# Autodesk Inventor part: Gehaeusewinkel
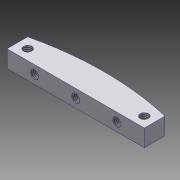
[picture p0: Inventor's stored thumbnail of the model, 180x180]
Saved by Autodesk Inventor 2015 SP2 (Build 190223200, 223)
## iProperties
Created: 2016-03
Part Number: Gehaeusewinkel
Material: Aluminum 6061
Document SubType Name: Modeling
Designer: rYan
Mass: 3.65288 g
Surface Area: 12.7601 cm^2
Volume: 1.35292 cm^3
Density: 2.7 g/cm^3
Appearance: Aluminum - Flat
Author: rYan
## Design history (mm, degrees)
sketch "Skizze5"
  geometry: L1 (-20, 0)-(20, 0); L2 (20, 0)-(20, 6); L3 (-20, 0)-(-20, 6); L4 (0, 25.73)-(0, -96.07) reference; L5 (-28, 0)-(28, 0) reference; A1 r 87 centre (0, -78.67) between (20, 6) and (-20, 6); 1 further point
  constraints: 6 end point, 2 point on circle, 1 centre point, 1 collinear, 1 horizontal, 1 perpendicular, 1 point on line, 1 vertical, 1 other
  dimensions: "d39" = 87 radius of A1; "d40" = 40 distance of L1.start L1.end; "d41" = 6 distance of L1.end L2.end
extrude "Extrusion2" new body sketch "Skizze5" distance "d42" = 5; taper "d43" = 0 deg
sketch "Skizze6"
  geometry: L1 (0, 0)-(40, 0) reference; L2 (40, 0)-(40, 5) reference; L3 (0, 5)-(40, 5) reference; L4 (0, 0)-(0, 5) reference; L5 (0, 2.5)-(40, 2.5); L6 (0, 5)-(40, 5) reference; L7 (20, 5)-(20, -0.175); 4 further points
  constraints: 4 end point, 4 midpoint, 3 point on line, 1 symmetric about line, 1 vertical
  dimensions: "d44" = 8 distance from line of L4 point (8, 2.5)
hole "Bohrung4" sketch "Skizze6" at (20, 2.5), (8, 2.5), (32, 2.5) diameter "d45" = 2.459; stored, may be unused: countersink angle "d49" = 90 deg, drill point angle "d51" = 118 deg; dims "d46" = 6, "d47" = 4, "d48" = 2, "d50" = 8
sketch "Skizze7"
  geometry: L1 (-20, 0)-(20, 0) reference; L2 (20, 0)-(20, 6) reference; L3 (-20, 6)-(-20, 0) reference; L4 (-17, 3)-(17, 3); L5 (0, 25.935)-(0, -97.303) reference; A1 r 87 centre (0, -78.67) between (20, 6) and (-20, 6) reference; 3 further points
  constraints: 2 coincident, 2 end point, 1 horizontal, 1 symmetric about line
  dimensions: "d60" = 3 distance between parallel lines of L1 L4; "d61" = 3 distance from line of L2 L4.end
hole "Bohrung5" sketch "Skizze7" at (-17, 3), (17, 3) diameter "d53" = 2.459; stored, may be unused: countersink angle "d57" = 90 deg, drill point angle "d59" = 118 deg; dims "d54" = 6, "d55" = 4, "d56" = 2, "d58" = 8
node "Volumenkörper2"
node "Projizierte Kontur4"
node "Projizierte Kontur5"
